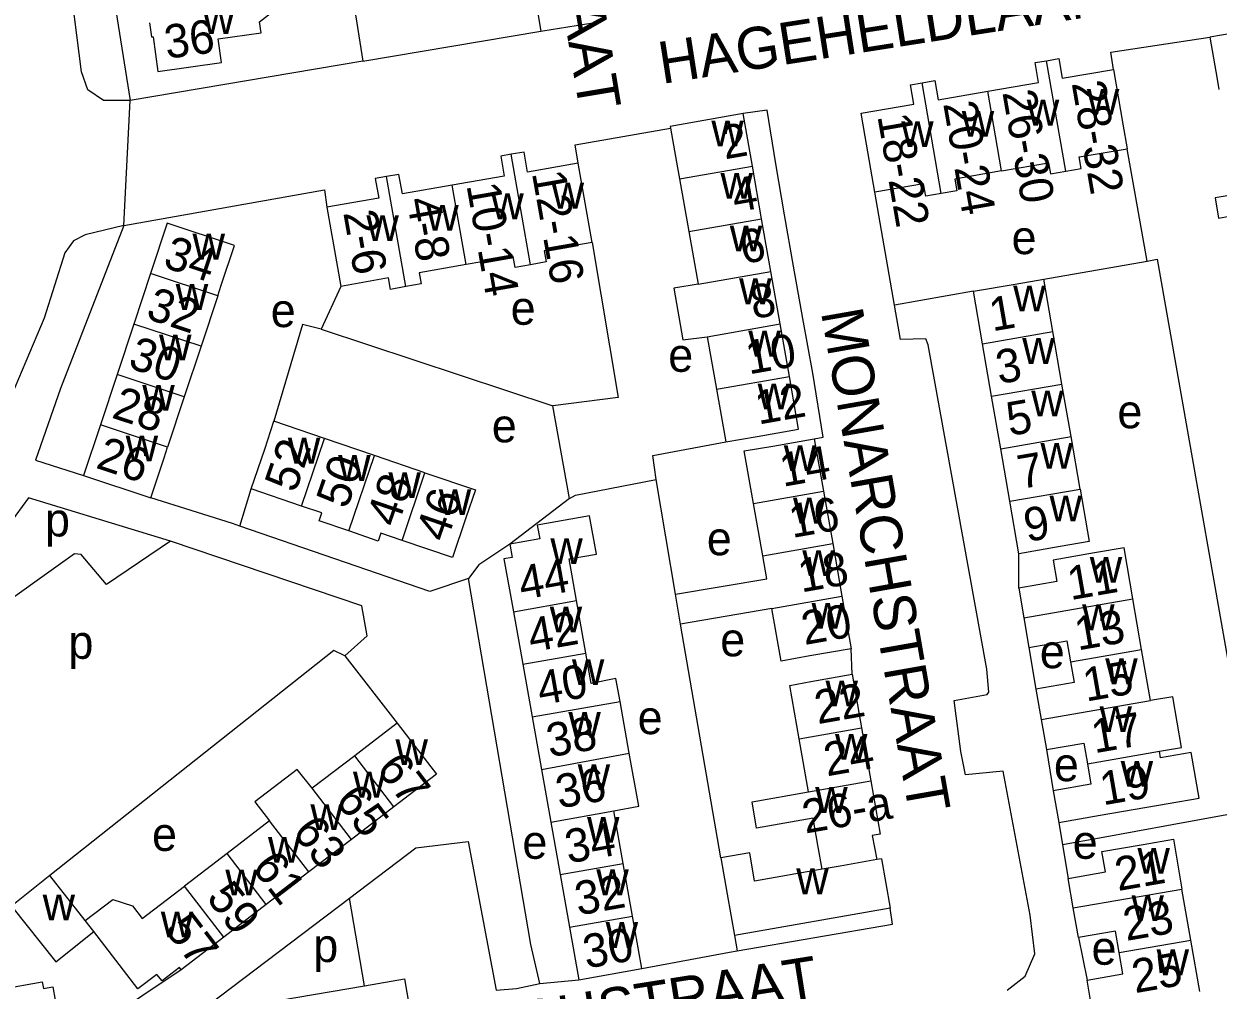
# Model space of a CAD drawing. Extents: x 162883 to 165538, y 383986 to 385172.
# Drawn here: x 164288.3 to 164430.6, y 384303.8 to 384419 of the extents above; entities that cross this region are included whole.
import ezdxf

# ---------------------------------------------------------------- set-up
doc = ezdxf.new("R2010")
doc.units = 0
for name, color, linetype in [('BLT_Basislijn', 7, 'Continuous'), ('BLT_Bebouwing', 7, 'Continuous'), ('BLT_Centroide', 7, 'Continuous'), ('BLT_Huisnummer', 7, 'Continuous'), ('BLT_Huisnummer_ tussenligend', 7, 'Continuous'), ('BLT_Huisnummer_reeks', 7, 'Continuous'), ('BLT_Onderverdeling_panden', 7, 'Continuous'), ('BLT_Straatnaam', 7, 'Continuous'), ('BLT_Vlakafsluiter', 7, 'Continuous')]:
    doc.layers.add(name, color=color, linetype=linetype)

msp = doc.modelspace()

# ---------------------------------------------------------------- linework, layer by layer
at = {"layer": 'BLT_Basislijn'}
for p, q in [((164349.27, 384421.7), (164349.87, 384418.18)), ((164328.67, 384414.58), (164349.87, 384418.18)), ((164328.67, 384414.58), (164300.94, 384409.91)), ((164376.86, 384408.77), (164374, 384408.34)), ((164422.17, 384390.76), (164419.77, 384404.16)), ((164392.06, 384385.5), (164389.71, 384398.97)), ((164409.83, 384388.61), (164422.17, 384390.76)), ((164326.03, 384387.74), (164323.69, 384382.64)), ((164401.45, 384387.16), (164392.06, 384385.5)), ((164323.69, 384382.64), (164351.33, 384373.49)), ((164353.3, 384362.46), (164351.33, 384373.49)), ((164314.02, 384359.16), (164315.35, 384363.61)), ((164365.95, 384351.04), (164363.63, 384364.7)), ((164353.3, 384362.46), (164346.19, 384357.02)), ((164346.19, 384357.02), (164342.48, 384354.54)), ((164406.85, 384351.76), (164406.87, 384355.87)), ((164371.35, 384319.61), (164366.55, 384347.47)), ((164326.53, 384343.71), (164332.77, 384335.66)), ((164386.98, 384341.51), (164386.88, 384344.55)), ((164408.07, 384344.69), (164408.88, 384339.74)), ((164410.14, 384332.51), (164410.96, 384327.62)), ((164411.61, 384323.84), (164412.07, 384321.15)), ((164412.07, 384321.15), (164412.74, 384317.16)), ((164328.86, 384304.36), (164327.08, 384314.8)), ((164372.97, 384310.37), (164373.29, 384308.52)), ((164413.96, 384310.12), (164414.99, 384305.04)), ((164349.78, 384304.64), (164354.41, 384305.07))]:
    msp.add_line(p, q, dxfattribs=at)
for points in [[(164300.94, 384409.91), (164297.77, 384409.92), (164295.9, 384411.19), (164295.12, 384413.33), (164293.49, 384426.14), (164290.57, 384449.19), (164286.27, 384482.86), (164283.36, 384500.58), (164282.34, 384505.46), (164281.79, 384510.79), (164282.4, 384514.2), (164283.23, 384515.73)], [(164320.05, 384462.68), (164327.08, 384424.68), (164328.67, 384414.58)], [(164299.02, 384427.53), (164298.96, 384422.43), (164300.94, 384409.91)], [(164349.87, 384418.18), (164350.12, 384418.23), (164356.09, 384419.16)], [(164418.16, 384413.62), (164417.83, 384415.67), (164429.62, 384417.45)], [(164382.48, 384369.57), (164383.52, 384369.76), (164382.3, 384377.39), (164381.13, 384383.92), (164380.01, 384390.16), (164378.93, 384396.28), (164377.9, 384402.36), (164376.86, 384408.77)], [(164354.34, 384402.44), (164353.96, 384404.61), (164365.35, 384406.6)], [(164300.18, 384395.02), (164324.09, 384399.26), (164324.37, 384397.17)], [(164300.18, 384395.02), (164295.59, 384393.9), (164294.19, 384393.19), (164293.14, 384391.74), (164290.67, 384383.96), (164285.39, 384371.56), (164279.22, 384361.24), (164270.12, 384349.98), (164261.4, 384340.32), (164243.74, 384320.55), (164240.78, 384317.34), (164238.38, 384313.16), (164237.93, 384309.92), (164238.95, 384305.82), (164241.62, 384301.03)], [(164300.18, 384395.02), (164292.63, 384375.55), (164289.67, 384367.04), (164295.39, 384365.2)], [(164356, 384392.99), (164359.11, 384374.51), (164351.33, 384373.49)], [(164422.17, 384390.76), (164423.35, 384390.97), (164434.9, 384325.32)], [(164405.49, 384303.83), (164407.6, 384305.52), (164408.77, 384308.16), (164408.23, 384312.79), (164404.99, 384329.94), (164400.52, 384329.5), (164399.93, 384332.28), (164399.17, 384338.37), (164403.09, 384339.09), (164403.28, 384339.37), (164403.05, 384342.11), (164396.04, 384380.78), (164395.76, 384381.49), (164392.77, 384381.42), (164392.06, 384385.5)], [(164323.69, 384382.64), (164321.47, 384383.18), (164318.06, 384371.69)], [(164363.63, 384364.7), (164363.24, 384367.58), (164371.93, 384369.2)], [(164353.3, 384362.46), (164354, 384362.84), (164363.63, 384364.7)], [(164305.73, 384357.37), (164288.83, 384362.54), (164280.49, 384351.18), (164272.89, 384342.84), (164273.08, 384340.7)], [(164314.02, 384359.16), (164313.15, 384359.46), (164303.4, 384362.55)], [(164341.25, 384352.91), (164336.65, 384351.37), (164314.02, 384359.16)], [(164305.73, 384357.37), (164298.1, 384352.2), (164295.09, 384355.79), (164294.3, 384355.87), (164273.08, 384340.7)], [(164326.53, 384343.71), (164329.17, 384346.09), (164328.53, 384349.64), (164305.73, 384357.37)], [(164342.48, 384354.54), (164341.25, 384352.91)], [(164349.78, 384304.64), (164348.71, 384309.29), (164341.25, 384352.91)], [(164326.53, 384343.71), (164325.2, 384344.32), (164291.34, 384317.5)], [(164434.9, 384325.32), (164425.15, 384323.55), (164416.49, 384321.97), (164412.07, 384321.15)], [(164327.08, 384314.8), (164334.99, 384320.79), (164341.21, 384321.55), (164344.55, 384303.85), (164346.99, 384304.02), (164349.78, 384304.64)], [(164308.77, 384300.94), (164327.08, 384314.8)], [(164373.29, 384308.52), (164391.82, 384311.69), (164391.51, 384313.63)], [(164361.93, 384306.4), (164372.36, 384308.36), (164373.29, 384308.52)], [(164307.02, 384306.28), (164297.65, 384300), (164295.89, 384298.72), (164301.44, 384264.05), (164297.47, 384263.31)], [(164328.86, 384304.36), (164333.63, 384305.17), (164334.46, 384300.31)], [(164308.77, 384300.94), (164328.86, 384304.36)]]:
    msp.add_lwpolyline(points, dxfattribs=at)
at = {"layer": 'BLT_Bebouwing'}
for p, q in [((164438.25, 384418.95), (164429.62, 384417.45)), ((164375.1, 384402.07), (164374, 384408.34)), ((164389.71, 384398.97), (164388.56, 384405.6)), ((164376.2, 384395.8), (164375.1, 384402.07)), ((164366.42, 384400.55), (164367.52, 384394.28)), ((164377.3, 384389.53), (164376.2, 384395.8)), ((164367.52, 384394.28), (164368.62, 384388.01)), ((164303.36, 384389.27), (164301.37, 384383.25)), ((164378.41, 384383.27), (164377.3, 384389.53)), ((164410.91, 384382.35), (164409.83, 384388.61)), ((164311.37, 384386.62), (164309.38, 384380.6)), ((164402.54, 384380.9), (164401.45, 384387.16)), ((164301.37, 384383.25), (164299.38, 384377.23)), ((164379.51, 384377), (164378.41, 384383.27)), ((164411.99, 384376.09), (164410.91, 384382.35)), ((164309.38, 384380.6), (164307.39, 384374.58)), ((164369.73, 384381.74), (164370.83, 384375.47)), ((164403.62, 384374.64), (164402.54, 384380.9)), ((164299.38, 384377.23), (164297.38, 384371.22)), ((164370.83, 384375.47), (164371.93, 384369.2)), ((164413.08, 384369.84), (164411.99, 384376.09)), ((164307.39, 384374.58), (164305.4, 384368.56)), ((164404.7, 384368.39), (164403.62, 384374.64)), ((164297.38, 384371.22), (164295.39, 384365.2)), ((164324.11, 384369.62), (164318.06, 384371.69)), ((164330.05, 384367.59), (164324.11, 384369.62)), ((164382.48, 384369.57), (164383.58, 384363.33)), ((164414.16, 384363.58), (164413.08, 384369.84)), ((164405.79, 384362.13), (164404.7, 384368.39)), ((164295.39, 384365.2), (164303.4, 384362.55)), ((164321.35, 384361.56), (164315.35, 384363.61)), ((164383.58, 384363.33), (164384.68, 384357.07)), ((164406.87, 384355.87), (164405.79, 384362.13)), ((164376.33, 384355.6), (164375.23, 384361.86)), ((164384.68, 384357.07), (164385.78, 384350.81)), ((164345.49, 384355.25), (164346.64, 384348.96)), ((164385.78, 384350.81), (164386.88, 384344.55)), ((164406.85, 384351.76), (164407.46, 384348.22)), ((164355.26, 384344.02), (164354.15, 384350.29)), ((164421.5, 384344.47), (164420.46, 384350.48)), ((164346.64, 384348.96), (164347.75, 384342.69)), ((164407.46, 384348.22), (164408.07, 384344.69)), ((164422.56, 384338.39), (164421.5, 384344.47)), ((164347.75, 384342.69), (164348.86, 384336.42)), ((164386.98, 384341.51), (164388.1, 384335.12)), ((164408.88, 384339.74), (164409.51, 384336.12)), ((164360.43, 384332.08), (164359.33, 384338.26)), ((164348.86, 384336.42), (164349.97, 384330.15)), ((164388.1, 384335.12), (164389.22, 384328.79)), ((164409.51, 384336.12), (164410.14, 384332.51)), ((164381.78, 384327.48), (164380.67, 384333.82)), ((164327.7, 384331.78), (164322.63, 384327.9)), ((164349.97, 384330.15), (164351.08, 384323.88)), ((164389.22, 384328.79), (164390.33, 384322.45)), ((164410.96, 384327.62), (164411.61, 384323.84)), ((164332.37, 384325.69), (164327.3, 384321.81)), ((164359.7, 384318.94), (164358.59, 384325.21)), ((164317.56, 384324.02), (164312.49, 384320.13)), ((164351.08, 384323.88), (164352.19, 384317.61)), ((164390.33, 384322.45), (164389.39, 384322.28)), ((164389.39, 384322.28), (164389.93, 384319.4)), ((164327.3, 384321.81), (164322.23, 384317.93)), ((164312.49, 384320.13), (164307.42, 384316.25)), ((164390.48, 384319.5), (164389.93, 384319.4)), ((164390.48, 384319.5), (164391.51, 384313.63)), ((164360.82, 384312.67), (164359.7, 384318.94)), ((164291.34, 384317.5), (164286.77, 384313.86)), ((164295.59, 384312.16), (164291.34, 384317.5)), ((164322.23, 384317.93), (164317.16, 384314.04)), ((164352.19, 384317.61), (164353.3, 384311.34)), ((164413.35, 384313.64), (164412.74, 384317.16)), ((164427.37, 384309.81), (164426.31, 384315.89)), ((164317.16, 384314.04), (164312.09, 384310.16)), ((164391.51, 384313.63), (164372.97, 384310.37)), ((164413.96, 384310.12), (164413.35, 384313.64)), ((164353.3, 384311.34), (164354.41, 384305.07)), ((164312.09, 384310.16), (164307.02, 384306.28)), ((164428.43, 384303.69), (164427.37, 384309.81)), ((164354.41, 384305.07), (164361.93, 384306.4)), ((164415.61, 384301.47), (164414.99, 384305.04))]:
    msp.add_line(p, q, dxfattribs=at)
for points in [[(164303.24, 384419.15), (164303.47, 384417.49), (164303.68, 384417.51), (164304.25, 384413.38), (164311.83, 384414.43), (164311.43, 384417.26), (164316.54, 384417.97), (164316.36, 384419.3), (164317.8, 384420.38), (164321.75, 384420.93), (164321.3, 384424.15), (164319.63, 384423.92)], [(164429.62, 384417.45), (164430.49, 384412.44), (164430.7, 384411.22)], [(164410.17, 384414.65), (164411.63, 384414.9), (164412.04, 384412.56), (164418.16, 384413.62)], [(164403.17, 384411), (164409.22, 384412.05), (164408.81, 384414.42), (164410.17, 384414.65)], [(164418.16, 384413.62), (164419.26, 384407.1), (164419.77, 384404.16)], [(164388.56, 384405.6), (164388.07, 384408.39), (164394.34, 384409.48), (164393.94, 384411.78), (164395.32, 384412.02)], [(164395.32, 384412.02), (164396.83, 384412.28), (164397.23, 384409.98), (164403.17, 384411)], [(164374, 384408.34), (164365.32, 384406.82), (164365.35, 384406.6)], [(164365.35, 384406.6), (164366.18, 384401.89), (164366.42, 384400.55)], [(164346.35, 384403.49), (164345.12, 384403.27), (164345.53, 384400.9), (164339.32, 384399.81)], [(164354.34, 384402.44), (164348.31, 384401.38), (164347.89, 384403.76), (164346.35, 384403.49)], [(164412.46, 384401.47), (164414.28, 384401.79), (164414.04, 384403.17), (164419.77, 384404.16)], [(164356, 384392.99), (164355.53, 384395.68), (164354.34, 384402.44)], [(164404.81, 384401.5), (164410.4, 384402.47), (164410.63, 384401.16), (164412.46, 384401.47)], [(164331.49, 384400.84), (164330.15, 384400.61), (164330.57, 384398.26), (164324.37, 384397.17)], [(164339.32, 384399.81), (164333.39, 384398.77), (164332.97, 384401.1), (164331.49, 384400.84)], [(164404.81, 384401.5), (164399.22, 384400.53), (164399.46, 384399.14), (164397.61, 384398.81)], [(164397.61, 384398.81), (164395.76, 384398.49), (164395.5, 384399.97), (164389.71, 384398.97)], [(164432.86, 384398.75), (164430.25, 384398.29), (164430.67, 384395.88), (164433.28, 384396.34), (164433.94, 384392.52)], [(164324.37, 384397.17), (164325.64, 384389.99), (164326.03, 384387.74)], [(164311.37, 384386.62), (164311.79, 384387.89), (164313.36, 384392.63), (164305.35, 384395.28), (164303.36, 384389.27)], [(164356, 384392.99), (164350.28, 384391.99), (164350.52, 384390.66), (164348.66, 384390.33)], [(164348.66, 384390.33), (164346.81, 384390), (164346.58, 384391.32), (164340.98, 384390.34)], [(164340.98, 384390.34), (164335.39, 384389.36), (164335.62, 384388.04), (164333.8, 384387.71)], [(164333.8, 384387.71), (164331.98, 384387.39), (164331.74, 384388.75), (164326.03, 384387.74)], [(164368.62, 384388.01), (164365.75, 384387.53), (164366.83, 384381.36), (164369.73, 384381.74)], [(164401.45, 384387.16), (164406.41, 384388.01), (164409.83, 384388.61)], [(164371.93, 384369.2), (164375.69, 384369.86), (164380.61, 384370.73), (164379.51, 384377)], [(164315.35, 384363.61), (164316.97, 384368.34), (164318.06, 384371.69)], [(164375.23, 384361.86), (164374.13, 384368.12), (164377.55, 384368.71), (164382.48, 384369.57)], [(164303.4, 384362.55), (164304.98, 384367.29), (164305.4, 384368.56)], [(164336.07, 384365.53), (164330.05, 384367.59)], [(164336.07, 384365.53), (164342.1, 384363.47), (164340.96, 384360.14), (164339.34, 384355.41), (164333.35, 384357.46)], [(164414.16, 384363.58), (164415.24, 384357.32), (164411.8, 384356.73), (164406.87, 384355.87)], [(164326.98, 384358.58), (164323.46, 384359.78), (164323.78, 384360.73), (164321.35, 384361.56)], [(164354.15, 384350.29), (164353.27, 384355.26), (164356.53, 384355.82), (164355.7, 384360.37), (164349.46, 384359.29), (164349.76, 384357.63), (164346.19, 384357.02)], [(164333.35, 384357.46), (164330.8, 384358.33), (164330.48, 384357.38), (164326.98, 384358.58)], [(164346.19, 384357.02), (164346.48, 384355.42), (164345.49, 384355.25)], [(164420.46, 384350.48), (164419.4, 384356.57), (164415.89, 384355.96), (164410.96, 384355.11), (164411.4, 384352.55), (164406.85, 384351.76)], [(164365.95, 384351.04), (164376.81, 384352.89), (164376.33, 384355.6)], [(164366.55, 384347.47), (164365.95, 384351.04)], [(164377.43, 384349.34), (164366.55, 384347.47)], [(164386.88, 384344.55), (164381.95, 384343.68), (164378.53, 384343.08), (164377.43, 384349.34)], [(164408.07, 384344.69), (164412.6, 384345.47), (164413.03, 384343)], [(164359.33, 384338.26), (164358.84, 384340.98), (164355.9, 384340.41), (164355.26, 384344.02)], [(164413.03, 384343), (164413.46, 384340.53), (164408.88, 384339.74)], [(164380.67, 384333.82), (164379.55, 384340.16), (164382.06, 384340.65), (164386.98, 384341.51)], [(164423.61, 384332.33), (164426.25, 384332.75), (164425.21, 384338.8), (164422.56, 384338.39)], [(164332.77, 384335.66), (164328.8, 384332.62), (164327.7, 384331.78)], [(164332.77, 384335.66), (164337.43, 384329.57), (164332.37, 384325.69)], [(164410.14, 384332.51), (164414.61, 384333.28), (164415.03, 384330.84)], [(164411.61, 384323.84), (164416.54, 384324.7), (164424.68, 384326.11), (164428.35, 384326.74), (164427.41, 384332.16), (164423.74, 384331.53), (164423.61, 384332.33)], [(164358.59, 384325.21), (164361.55, 384325.78), (164360.43, 384332.08)], [(164415.03, 384330.84), (164415.45, 384328.4), (164410.96, 384327.62)], [(164322.63, 384327.9), (164320.83, 384330.16), (164315.78, 384326.3), (164317.56, 384324.02)], [(164383.42, 384318.26), (164382.89, 384321.14), (164382.33, 384324.34), (164375.61, 384323.16), (164375.06, 384326.3), (164381.78, 384327.48)], [(164412.74, 384317.16), (164417.18, 384317.93), (164416.76, 384320.35), (164421.69, 384321.2), (164425.28, 384321.82), (164426.31, 384315.89)], [(164383.42, 384318.26), (164375.37, 384316.84), (164374.78, 384320.21), (164371.35, 384319.61)], [(164371.35, 384319.61), (164372.11, 384315.29), (164372.97, 384310.37)], [(164295.59, 384312.16), (164298.85, 384314.65), (164301.2, 384313.88), (164302.35, 384312.37), (164307.42, 384316.25)], [(164286.77, 384313.86), (164292.06, 384307.21), (164296.61, 384310.83)], [(164361.93, 384306.4), (164361.05, 384311.33), (164360.82, 384312.67)], [(164418.81, 384308.33), (164418.37, 384310.88), (164413.96, 384310.12)], [(164307.02, 384306.28), (164306.83, 384306.53), (164304.74, 384304.93), (164304.13, 384305.72), (164301.86, 384303.98), (164296.61, 384310.83)], [(164414.99, 384305.04), (164419.26, 384305.78), (164418.81, 384308.33)], [(164270.2, 384298.36), (164279.16, 384299.94), (164278.66, 384302.78), (164285.54, 384303.97), (164290.46, 384304.84), (164290.6, 384304.05), (164291.7, 384304.25), (164292.27, 384301.07), (164291.16, 384300.88), (164291.59, 384298.45)]]:
    msp.add_lwpolyline(points, dxfattribs=at)
at = {"layer": 'BLT_Onderverdeling_panden'}
for p, q in [((164412.46, 384401.47), (164410.17, 384414.65)), ((164397.61, 384398.81), (164395.32, 384412.02)), ((164404.81, 384401.5), (164403.17, 384411)), ((164348.66, 384390.33), (164346.35, 384403.49)), ((164366.42, 384400.55), (164375.1, 384402.07)), ((164333.8, 384387.71), (164331.49, 384400.84)), ((164340.98, 384390.34), (164339.32, 384399.81)), ((164367.52, 384394.28), (164376.2, 384395.8)), ((164311.37, 384386.62), (164303.36, 384389.27)), ((164368.62, 384388.01), (164377.3, 384389.53)), ((164309.38, 384380.6), (164301.37, 384383.25)), ((164369.73, 384381.74), (164378.41, 384383.27)), ((164402.54, 384380.9), (164410.91, 384382.35)), ((164307.39, 384374.58), (164299.38, 384377.23)), ((164370.83, 384375.47), (164379.51, 384377)), ((164403.62, 384374.64), (164411.99, 384376.09)), ((164305.4, 384368.56), (164297.38, 384371.22)), ((164321.35, 384361.56), (164324.11, 384369.62)), ((164404.7, 384368.39), (164413.08, 384369.84)), ((164326.98, 384358.58), (164330.05, 384367.59)), ((164333.35, 384357.46), (164336.07, 384365.53)), ((164405.79, 384362.13), (164414.16, 384363.58)), ((164375.23, 384361.86), (164383.58, 384363.33)), ((164376.33, 384355.6), (164384.68, 384357.07)), ((164377.43, 384349.34), (164385.78, 384350.81)), ((164346.64, 384348.96), (164354.15, 384350.29)), ((164407.46, 384348.22), (164420.46, 384350.48)), ((164347.75, 384342.69), (164355.26, 384344.02)), ((164413.03, 384343), (164421.5, 384344.47)), ((164348.86, 384336.42), (164359.33, 384338.26)), ((164409.51, 384336.12), (164422.56, 384338.39)), ((164380.67, 384333.82), (164388.1, 384335.12)), ((164415.03, 384330.84), (164423.61, 384332.33)), ((164332.37, 384325.69), (164327.7, 384331.78)), ((164349.97, 384330.15), (164360.43, 384332.08)), ((164381.78, 384327.48), (164389.22, 384328.79)), ((164327.3, 384321.81), (164322.63, 384327.9)), ((164351.08, 384323.88), (164358.59, 384325.21)), ((164322.23, 384317.93), (164317.56, 384324.02)), ((164317.16, 384314.04), (164312.49, 384320.13)), ((164352.19, 384317.61), (164359.7, 384318.94)), ((164312.09, 384310.16), (164307.42, 384316.25)), ((164413.35, 384313.64), (164426.31, 384315.89)), ((164353.3, 384311.34), (164360.82, 384312.67)), ((164296.61, 384310.83), (164295.59, 384312.16)), ((164418.81, 384308.33), (164427.37, 384309.81))]:
    msp.add_line(p, q, dxfattribs=at)
msp.add_lwpolyline([(164389.93, 384319.4), (164385.55, 384318.63), (164383.42, 384318.26)], dxfattribs=at)
at = {"layer": 'BLT_Vlakafsluiter'}
msp.add_line((164300.18, 384395.02), (164300.94, 384409.91), dxfattribs=at)

# ---------------------------------------------------------------- texts
at = {"layer": 'BLT_Centroide'}
for s, p in [('w', (164309.55, 384417.84)), ('w', (164414.97, 384408.2)), ('w', (164407.81, 384406.92)), ('w', (164400.06, 384405.58)), ('w', (164370.21, 384404.44)), ('w', (164392.84, 384404.36)), ('w', (164371.3, 384398.19)), ('w', (164351.17, 384397.02)), ('w', (164343.98, 384395.75)), ('w', (164336.23, 384394.39)), ('w', (164329.09, 384393.14)), ('w', (164372.41, 384391.91)), ('w', (164308.37, 384390.94)), ('e', (164406, 384391.59)), ('w', (164306.37, 384384.94)), ('w', (164373.52, 384385.62)), ('w', (164406.19, 384384.75)), ('e', (164346.29, 384383.17)), ('e', (164317.69, 384382.89)), ('w', (164374.62, 384379.38)), ('w', (164304.38, 384378.91)), ('e', (164365.07, 384377.56)), ('w', (164407.27, 384378.5)), ('w', (164302.38, 384372.91)), ('w', (164375.72, 384373.09)), ('w', (164408.34, 384372.25)), ('e', (164418.61, 384370.83)), ('e', (164344.04, 384369.15)), ('w', (164300.4, 384366.88)), ('w', (164319.73, 384366.62)), ('w', (164378.85, 384365.72)), ('w', (164409.44, 384366)), ('w', (164325.73, 384364.56)), ('w', (164331.72, 384362.5)), ('w', (164337.72, 384360.47)), ('w', (164379.95, 384359.47)), ('w', (164410.52, 384359.72)), ('p', (164290.78, 384357.93)), ('e', (164369.67, 384355.69)), ('w', (164351.02, 384354.64)), ('w', (164381.05, 384353.22)), ('w', (164415.32, 384352.41)), ('w', (164350.95, 384346.5)), ('w', (164382.15, 384346.94)), ('w', (164414.41, 384346.75)), ('p', (164293.58, 384343.34)), ('e', (164371.27, 384343.64)), ('e', (164409.36, 384342.22)), ('w', (164353.59, 384340.22)), ('w', (164417.16, 384340.31)), ('w', (164383.82, 384337.66)), ('w', (164353.17, 384333.94)), ('e', (164361.42, 384334.36)), ('w', (164416.48, 384334.62)), ('w', (164332.56, 384330.67)), ('w', (164384.95, 384331.31)), ('e', (164411.04, 384328.75)), ('w', (164419, 384328.09)), ('w', (164327.5, 384326.8)), ('w', (164354.28, 384327.69)), ('w', (164382.59, 384324.97)), ('w', (164322.42, 384322.92)), ('w', (164355.39, 384321.41)), ('e', (164303.54, 384320.44)), ('e', (164347.69, 384319.5)), ('e', (164413.29, 384319.5)), ('w', (164317.36, 384319.03)), ('w', (164421, 384317.72)), ('w', (164312.28, 384315.14)), ('w', (164356.5, 384315.16)), ('w', (164380.33, 384315.28)), ('w', (164290.5, 384312.17)), ('w', (164420.29, 384312.09)), ('w', (164304.59, 384310.12)), ('w', (164357.61, 384308.88)), ('p', (164322.76, 384307.19)), ('e', (164415.53, 384306.87)), ('w', (164423.28, 384305.62))]:
    msp.add_text(s, height=4, dxfattribs=at).set_placement(p)
at = {"layer": 'BLT_Huisnummer'}
for s, rotation, p in [('36', 7.9045, (164305.3, 384414.86)), ('2', 9.9711, (164371.82, 384402.88)), ('34', 341.6831, (164304.7, 384390.09)), ('6', 9.9711, (164373.98, 384390.39)), ('1', 9.8314, (164403.71, 384382.37)), ('30', 341.6831, (164300.54, 384378.09)), ('12', 9.9711, (164375.82, 384371.26)), ('5', 9.8314, (164405.75, 384369.9)), ('26', 341.6831, (164296.71, 384366.14)), ('52', 71.1183, (164320.64, 384363.03)), ('14', 9.9711, (164378.74, 384363.84)), ('46', 71.123, (164338.65, 384357.1)), ('9', 9.8314, (164407.83, 384357.26)), ('44', 10.0523, (164347.61, 384350.36)), ('11', 9.8314, (164413.02, 384350.33)), ('20', 9.9711, (164381.31, 384344.98)), ('15', 9.8404, (164414.87, 384338.23)), ('22', 9.9711, (164382.89, 384335.54)), ('38', 10.0523, (164350.94, 384331.59)), ('67', 307.4434, (164330.17, 384330.22)), ('19', 9.8404, (164416.89, 384325.86)), ('34', 10.0523, (164353.15, 384318.93)), ('61', 307.4375, (164315.33, 384318.45)), ('21', 9.8404, (164418.68, 384315.65)), ('57', 307.4428, (164304.93, 384311.06)), ('30', 10.0523, (164355.3, 384306.4)), ('25', 9.8404, (164420.71, 384303.47))]:
    msp.add_text(s, height=4, rotation=rotation, dxfattribs=at).set_placement(p)
at = {"layer": 'BLT_Huisnummer_ tussenligend'}
for s, rotation, p in [('4', 9.9711, (164373.03, 384396.55)), ('8', 9.9711, (164375.21, 384383.84)), ('32', 341.6831, (164302.66, 384383.96)), ('10', 9.9711, (164374.69, 384377.24)), ('3', 9.8314, (164404.49, 384376.09)), ('28', 341.6831, (164298.6, 384372.13)), ('7', 9.8314, (164407.07, 384363.58)), ('50', 71.123, (164326.79, 384361.09)), ('48', 71.123, (164332.78, 384358.88)), ('16', 9.9711, (164379.85, 384357.74)), ('18', 9.9711, (164380.93, 384351.24)), ('42', 10.0523, (164348.73, 384344.12)), ('13', 9.8404, (164413.88, 384344.33)), ('40', 10.0523, (164349.83, 384337.8)), ('17', 9.8404, (164415.88, 384332.07)), ('24', 9.9711, (164383.98, 384329.32)), ('36', 10.0523, (164352.05, 384325.48)), ('65', 307.4375, (164325.26, 384326.46)), ('63', 307.4375, (164320.16, 384322.69)), ('59', 307.4428, (164309.92, 384314.83)), ('32', 10.0523, (164354.32, 384312.73)), ('23', 9.8404, (164419.67, 384309.7))]:
    msp.add_text(s, height=4, rotation=rotation, dxfattribs=at).set_placement(p)
at = {"layer": 'BLT_Huisnummer_reeks'}
for s, rotation, p in [('28-32', 279.8355, (164413.15, 384411.98)), ('26-30', 279.8256, (164404.89, 384410.88)), ('20-24', 279.8327, (164397.84, 384409.53)), ('18-22', 279.8307, (164389.99, 384408.06)), ('12-16', 279.9707, (164348.81, 384401.26)), ('10-14', 279.9659, (164341.01, 384399.81)), ('4-8', 279.9831, (164333.88, 384398.09)), ('2-6', 279.9729, (164326.33, 384396.53)), ('26-a', 9.9711, (164381.41, 384322.5))]:
    msp.add_text(s, height=4, rotation=rotation, dxfattribs=at).set_placement(p)
at = {"layer": 'BLT_Straatnaam'}
for s, height, rotation, p in [('KLUIZENAARSTRAAT', 5, 279.4388, (164343.33, 384475.93)), ('HAGEHELDLAAN', 5, 8.917, (164364.33, 384411.87)), ('MONARCHSTRAAT', 4.9999, 279.9721, (164383.26, 384384.7)), ('MONARCHSTRAAT', 5, 8.989, (164323.01, 384293.49))]:
    msp.add_text(s, height=height, rotation=rotation, dxfattribs=at).set_placement(p)

doc.saveas('drawing.dxf')
